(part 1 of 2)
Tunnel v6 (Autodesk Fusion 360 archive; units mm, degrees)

design "Tunnel" references "Air_intake", "Electronics Housing", "fan housing", "Air_Strainer_holder", "Air_out_Strainer", "HC002", "Testing section", "Fam2defuser", "M4x30 Hex"
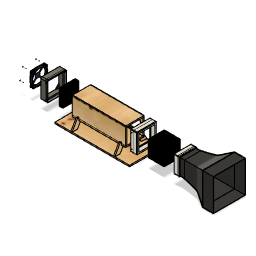
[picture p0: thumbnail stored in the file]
component_insert "Component Insert1"
component_insert "Component Insert2"
component_insert "Component Insert3"
component_insert "Component Insert4"
component_insert "Component Insert6"
component_insert "Component Insert8"
component_insert "Component Insert9"
component_insert "Component Insert10"
component_insert "Component Insert11"
component_insert "Component Insert12"
component_insert "Component Insert13"
component_insert "Component Insert14"

design "M4x30 Hex"
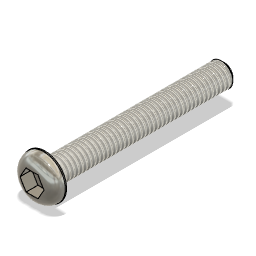
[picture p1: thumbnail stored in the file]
sketch "Sketch1" plane through (0, 0, 0) normal (0, 0, 1) x axis (1, 0, 0)
  circle C1 centre (0, 0) radius 2
  point P1 (0, 0)
  point P2 (0, 0)
  coincident P1 P2
  dimension "d1" diameter C1 = 4
extrude "Extrude1" new body sketch "Sketch1" along normal blind 30
sketch "Sketch2" plane through (0, 0, 30) normal (0, 0, 1) x axis (1, 0, 0)
  circle C1 centre (0, 0) radius 2
  circle C2 centre (0, 0) radius 3.62
  point P1 (0, 0)
  point P3 (0, 0)
  coincident P1 P3
  dimension "d4" diameter C2 = 7.24
extrude "Extrude2" add sketch "Sketch2" along normal blind 2.2
fillet "Fillet1" radius 2
sketch "Sketch3" plane through (0, 0, 32.2) normal (0, 0, 1) x axis (1, 0, 0)
  line L1 (0, -1.62) -> (0, 1.62)
  line L2 (1.62, 0) -> (-1.62, 0)
  line L3 (-1.0142, 1.7238) -> (0.9857, 1.7402)
  line L4 (-1.9999, -0.0164) -> (-1.0142, 1.7238)
  line L5 (-0.9857, -1.7402) -> (-1.9999, -0.0164)
  line L6 (1.0142, -1.7238) -> (-0.9857, -1.7402)
  line L7 (1.9999, 0.0164) -> (1.0142, -1.7238)
  line L8 (0.9857, 1.7402) -> (1.9999, 0.0164)
  circle C1 centre (0, 0) radius 1.62
  point P3 (0, 1.62)
  point P4 (0, -1.62)
  point P5 (-1.62, 0)
  point P6 (1.62, 0)
  point P1 (0, 0)
  point P13 (0, 0)
  point P7 (0.9857, 1.7402)
  coincident C1 P3
  coincident C1 P4
  vertical L1
  coincident C1 P5
  coincident C1 P6
  perpendicular L1 L2
  coincident P1 P13
  dimension "d9" distance P7 P13 = 2
extrude "Extrude3" cut sketch "Sketch3" profile of C1 L3 L4 L5 L6 L7 L8 against normal blind 2
thread "Thread1" ThreadOffset 0 ThreadLength 10
chamfer "Chamfer1" distance 0.5

design "PBC"
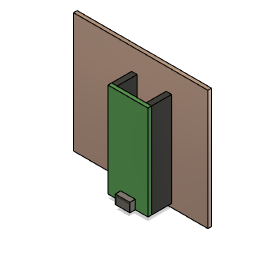
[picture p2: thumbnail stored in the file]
sketch "Sketch1" plane through (0, 0, 0) normal (0, 0, 1) x axis (1, 0, 0)
  line L1 (74, 0) -> (0, 0)
  line L2 (74, 66) -> (74, 0)
  line L3 (0, 66) -> (74, 66)
  line L4 (0, 0) -> (0, 66)
  point P1 (0, 0)
  point P2 (0, 0)
  point P3 (74, 0)
  point P4 (74, 66)
  point P5 (0, 66)
  horizontal L1
  vertical L2
  horizontal L3
  vertical L4
  coincident P1 P2
  dimension "d1" distance P3 P4 = 66
  dimension "d2" distance P4 P5 = 74
extrude "Extrude1" new body sketch "Sketch1" along normal blind 2
sketch "Sketch2" plane through (0, 0, 2) normal (0, 0, 1) x axis (1, 0, 0)
  line L1 (0, 0) -> (0, 66)
  line L2 (74, 0) -> (0, 0)
  line L3 (74, 66) -> (74, 0)
  line L4 (0, 66) -> (74, 66)
  line L5 (54, 54) -> (51, 54)
  line L6 (54, 2) -> (54, 54)
  line L7 (51, 2) -> (54, 2)
  line L8 (51, 54) -> (51, 2)
  line L9 (35, 54) -> (32, 54)
  line L10 (35, 2) -> (35, 54)
  line L11 (32, 2) -> (35, 2)
  line L12 (32, 54) -> (32, 2)
  point P10 (32, 54)
  point P11 (35, 54)
  point P12 (35, 2)
  point P7 (54, 54)
  point P8 (54, 2)
  horizontal L5
  vertical L6
  horizontal L7
  vertical L8
  horizontal L9
  vertical L10
  horizontal L11
  vertical L12
  dimension "d5" distance L3 L6 = 20
  dimension "d6" distance L6 L8 = 3
  dimension "d7" distance P10 P11 = 3
  dimension "d8" distance L6 L12 = 22
  dimension "d9" distance P10 P12 = 52
  dimension "d10" distance P7 P8 = 52
  dimension "d11" distance L4 P10 = 12
  dimension "d12" distance L4 L5 = 12
extrude "Extrude2" new body sketch "Sketch2" profile of L5 L6 L7 L8 L9 L10 L11 L12 along normal blind 11
work_plane "WorkPlane1" AlongDistance 0
sketch "Sketch3" plane through (0, 0, 13) normal (0, 0, 1) x axis (1, 0, 0)
  line L1 (32, 2) -> (32, 54)
  line L2 (54, 54) -> (54, 2)
  line L3 (54, 54) -> (32, 54)
  line L4 (54, 2) -> (54, 54)
  line L5 (32, 2) -> (54, 2)
  line L6 (32, 54) -> (32, 2)
  point P4 (54, 2)
  point P8 (54, 2)
  point P2 (32, 54)
  point P6 (32, 54)
  horizontal L3
  vertical L4
  horizontal L5
  vertical L6
  coincident P4 P8
  coincident P2 P6
extrude "Extrude3" new body sketch "Sketch3" along normal blind 2
sketch "Sketch4" plane through (0, 0, 15) normal (0, 0, 1) x axis (1, 0, 0)
  line L1 (54, 2) -> (32, 2)
  line L2 (54, 54) -> (54, 2)
  line L3 (32, 54) -> (54, 54)
  line L4 (32, 2) -> (32, 54)
  line L5 (43, 54) -> (43, 2)
  line L6 (47, 2) -> (39, 2)
  line L7 (47, 7) -> (47, 2)
  line L8 (39, 7) -> (47, 7)
  line L9 (39, 2) -> (39, 7)
  point P6 (43, 2)
  point P7 (43, 54)
  point P8 (39, 2)
  point P11 (39, 7)
  point P10 (47, 7)
  midpoint L1 P6
  midpoint L3 P7
  horizontal L6
  vertical L7
  horizontal L8
  vertical L9
  coincident L1 P8
  symmetric L5 L7 L9
  dimension "d18" distance P8 P11 = 5
  dimension "d19" distance P10 P11 = 8
extrude "Extrude4" new body sketch "Sketch4" profile of L1 L5 L6 L7 L8 L9 along normal blind 3
sketch "Sketch5" plane through (0, 2, 0) normal (0, -1, 0) x axis (1, 0, 0)
  line L1 (47, 15) -> (39, 15)
  line L2 (47, 18) -> (47, 15)
  line L3 (39, 18) -> (47, 18)
  line L4 (39, 15) -> (39, 18)
  line L5 (45.5, 17.2106) -> (40.5, 17.2106)
  line L6 (45.5, 16.6106) -> (45.5, 17.2106)
  line L7 (40.5, 16.6106) -> (45.5, 16.6106)
  line L8 (40.5, 17.2106) -> (40.5, 16.6106)
  line L9 (43, 15) -> (43, 18)
  line L10 (46.5833, 17.6974) -> (39.4167, 17.6974)
  line L11 (46.5833, 15.3264) -> (46.5833, 17.6974)
  line L12 (39.4167, 15.3264) -> (46.5833, 15.3264)
  line L13 (39.4167, 17.6974) -> (39.4167, 15.3264)
  point P10 (43, 18)
  point P11 (43, 15)
  point P6 (40.5, 17.2106)
  point P7 (45.5, 17.2106)
  horizontal L5
  vertical L6
  horizontal L7
  vertical L8
  midpoint L3 P10
  midpoint L1 P11
  symmetric L6 L8 L9
  horizontal L10
  vertical L11
  horizontal L12
  vertical L13
  symmetric L9 L11 L13
  dimension "d22" distance L5 L7 = 0.6
  dimension "d23" distance P6 P7 = 5
  dimension "d24" distance L1 L7 = 1.6106
  dimension "d25" distance L1 L12 = 0.3264
  dimension "d26" distance L4 L13 = 0.4167
  dimension "d27" distance L10 L12 = 2.371
extrude "Extrude5" cut sketch "Sketch5" profile of L5 L6 L7 L8 L9 L10 L11 L12 L13 against normal blind 4
sketch "Sketch6" plane through (0, 0, 0) normal (0, 1, 0) x axis (1, 0, 0)

design "Air_Strainer_holder"
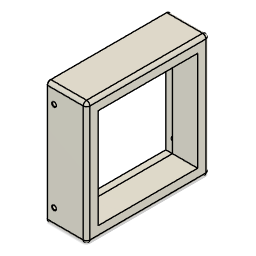
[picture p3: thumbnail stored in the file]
named bodies: "Airstrinder Holder"

design "HC002"
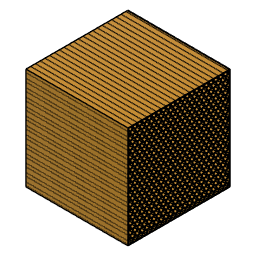
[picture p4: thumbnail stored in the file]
sketch "Sketch1" plane through (0, 0, 0) normal (1, 0, 0) x axis (0, 0, -1)
  line L1 (-75, 75) -> (75, 75)
  line L2 (-75, -75) -> (-75, 75)
  line L3 (75, -75) -> (-75, -75)
  line L4 (75, 75) -> (75, -75)
  line L5 (-75, -75) -> (75, 75)
  line L6 (75, -75) -> (-75, 75)
  line L7 (-71.3532, -71.3532) -> (0, 0)
  line L8 (-68.3532, -69.6211) -> (-68.3532, -73.0852)
  line L9 (-71.3532, -67.8891) -> (-68.3532, -69.6211)
  line L10 (-74, -69.4172) -> (-71.3532, -67.8891)
  line L11 (-72.7687, -74) -> (-74, -73.2891)
  line L12 (-68.3532, -73.0852) -> (-69.9376, -74)
  line L13 (-67.7706, -68.8181) -> (-70.7706, -67.0861)
  line L14 (-64.7706, -67.0861) -> (-67.7706, -68.8181)
  line L15 (-70.7706, -67.0861) -> (-70.7706, -63.622)
  line L16 (-64.7706, -63.622) -> (-64.7706, -67.0861)
  line L17 (-67.7706, -61.8899) -> (-64.7706, -63.622)
  line L18 (-70.7706, -63.622) -> (-67.7706, -61.8899)
  line L19 (-71.3532, -79.3958) -> (-71.3532, -71.3532)
  line L20 (-67.3532, -73.0852) -> (-67.3532, -69.6211)
  line L21 (-65.7687, -74) -> (-67.3532, -73.0852)
  line L22 (-61.3532, -73.0852) -> (-62.9376, -74)
  line L23 (-61.3532, -69.6211) -> (-61.3532, -73.0852)
  line L24 (-64.3532, -67.8891) -> (-61.3532, -69.6211)
  line L25 (-67.3532, -69.6211) -> (-64.3532, -67.8891)
  line L26 (-57.7706, -63.622) -> (-57.7706, -67.0861)
  line L27 (-60.7706, -61.8899) -> (-57.7706, -63.622)
  line L28 (-63.7706, -63.622) -> (-60.7706, -61.8899)
  line L29 (-63.7706, -67.0861) -> (-63.7706, -63.622)
  line L30 (-60.7706, -68.8181) -> (-63.7706, -67.0861)
  line L31 (-57.7706, -67.0861) -> (-60.7706, -68.8181)
  line L32 (-50.3532, -67.8891) -> (-47.3532, -69.6211)
  line L33 (-53.3532, -69.6211) -> (-50.3532, -67.8891)
  line L34 (-51.7687, -74) -> (-53.3532, -73.0852)
  line L35 (-47.3532, -73.0852) -> (-48.9376, -74)
  line L36 (-47.3532, -69.6211) -> (-47.3532, -73.0852)
  line L37 (-53.3532, -73.0852) -> (-53.3532, -69.6211)
  line L38 (-54.3532, -73.0852) -> (-55.9376, -74)
  line L39 (-57.3532, -67.8891) -> (-54.3532, -69.6211)
  line L40 (-60.3532, -69.6211) -> (-57.3532, -67.8891)
  line L41 (-58.7687, -74) -> (-60.3532, -73.0852)
  line L42 (-60.3532, -73.0852) -> (-60.3532, -69.6211)
  line L43 (-54.3532, -69.6211) -> (-54.3532, -73.0852)
  line L44 (-36.3532, -67.8891) -> (-33.3532, -69.6211)
  line L45 (-39.3532, -69.6211) -> (-36.3532, -67.8891)
  line L46 (-37.7687, -74) -> (-39.3532, -73.0852)
  line L47 (-33.3532, -73.0852) -> (-34.9376, -74)
  line L48 (-33.3532, -69.6211) -> (-33.3532, -73.0852)
  line L49 (-39.3532, -73.0852) -> (-39.3532, -69.6211)
  line L50 (-40.3532, -73.0852) -> (-41.9376, -74)
  line L51 (-43.3532, -67.8891) -> (-40.3532, -69.6211)
  line L52 (-46.3532, -69.6211) -> (-43.3532, -67.8891)
  line L53 (-44.7687, -74) -> (-46.3532, -73.0852)
  line L54 (-46.3532, -73.0852) -> (-46.3532, -69.6211)
  line L55 (-40.3532, -69.6211) -> (-40.3532, -73.0852)
  line L56 (-53.7706, -61.8899) -> (-50.7706, -63.622)
  line L57 (-56.7706, -63.622) -> (-53.7706, -61.8899)
  line L58 (-56.7706, -67.0861) -> (-56.7706, -63.622)
  line L59 (-53.7706, -68.8181) -> (-56.7706, -67.0861)
  line L60 (-50.7706, -67.0861) -> (-53.7706, -68.8181)
  line L61 (-50.7706, -63.622) -> (-50.7706, -67.0861)
  line L62 (-49.7706, -67.0861) -> (-49.7706, -63.622)
  line L63 (-46.7706, -68.8181) -> (-49.7706, -67.0861)
  line L64 (-43.7706, -67.0861) -> (-46.7706, -68.8181)
  line L65 (-43.7706, -63.622) -> (-43.7706, -67.0861)
  line L66 (-46.7706, -61.8899) -> (-43.7706, -63.622)
  line L67 (-49.7706, -63.622) -> (-46.7706, -61.8899)
  line L68 (-39.7706, -61.8899) -> (-36.7706, -63.622)
  line L69 (-42.7706, -63.622) -> (-39.7706, -61.8899)
  line L70 (-42.7706, -67.0861) -> (-42.7706, -63.622)
  line L71 (-39.7706, -68.8181) -> (-42.7706, -67.0861)
  line L72 (-36.7706, -67.0861) -> (-39.7706, -68.8181)
  line L73 (-36.7706, -63.622) -> (-36.7706, -67.0861)
  line L74 (-35.7706, -67.0861) -> (-35.7706, -63.622)
  line L75 (-32.7706, -68.8181) -> (-35.7706, -67.0861)
  line L76 (-29.7706, -67.0861) -> (-32.7706, -68.8181)
  line L77 (-29.7706, -63.622) -> (-29.7706, -67.0861)
  line L78 (-32.7706, -61.8899) -> (-29.7706, -63.622)
  line L79 (-35.7706, -63.622) -> (-32.7706, -61.8899)
  line L80 (9.2294, -61.8899) -> (12.2294, -63.622)
  line L81 (12.2294, -63.622) -> (12.2294, -67.0861)
  line L82 (-0.7706, -63.622) -> (2.2294, -61.8899)
  line L83 (2.6468, -73.0852) -> (2.6468, -69.6211)
  line L84 (-4.3532, -69.6211) -> (-1.3532, -67.8891)
  line L85 (1.6468, -69.6211) -> (1.6468, -73.0852)
  line L86 (-14.7706, -63.622) -> (-11.7706, -61.8899)
  line L87 (-25.7706, -61.8899) -> (-22.7706, -63.622)
  line L88 (-5.3532, -73.0852) -> (-6.9376, -74)
  line L89 (-2.7687, -74) -> (-4.3532, -73.0852)
  line L90 (-7.7706, -63.622) -> (-4.7706, -61.8899)
  line L91 (-0.7706, -67.0861) -> (-0.7706, -63.622)
  line L92 (5.2294, -67.0861) -> (2.2294, -68.8181)
  line L93 (-8.3532, -67.8891) -> (-5.3532, -69.6211)
  line L94 (2.2294, -68.8181) -> (-0.7706, -67.0861)
  line L95 (2.6468, -69.6211) -> (5.6468, -67.8891)
  line L96 (-4.7706, -61.8899) -> (-1.7706, -63.622)
  line L97 (8.6468, -69.6211) -> (8.6468, -73.0852)
  line L98 (-21.7706, -63.622) -> (-18.7706, -61.8899)
  line L99 (1.6468, -73.0852) -> (0.0624, -74)
  line L100 (-7.7706, -67.0861) -> (-7.7706, -63.622)
  line L101 (-18.7706, -61.8899) -> (-15.7706, -63.622)
  line L102 (5.2294, -63.622) -> (5.2294, -67.0861)
  line L103 (4.2313, -74) -> (2.6468, -73.0852)
  line L104 (-28.7706, -63.622) -> (-25.7706, -61.8899)
  line L105 (2.2294, -61.8899) -> (5.2294, -63.622)
  line L106 (6.2294, -63.622) -> (9.2294, -61.8899)
  line L107 (-11.7706, -61.8899) -> (-8.7706, -63.622)
  line L108 (12.2294, -67.0861) -> (9.2294, -68.8181)
  line L109 (-1.3532, -67.8891) -> (1.6468, -69.6211)
  line L110 (-8.7706, -67.0861) -> (-11.7706, -68.8181)
  line L111 (-11.3532, -69.6211) -> (-8.3532, -67.8891)
  line L112 (-9.7687, -74) -> (-11.3532, -73.0852)
  line L113 (-1.7706, -63.622) -> (-1.7706, -67.0861)
  line L114 (8.6468, -73.0852) -> (7.0624, -74)
  line L115 (-1.7706, -67.0861) -> (-4.7706, -68.8181)
  line L116 (5.6468, -67.8891) -> (8.6468, -69.6211)
  line L117 (-4.7706, -68.8181) -> (-7.7706, -67.0861)
  line L118 (-11.7706, -68.8181) -> (-14.7706, -67.0861)
  line L119 (6.2294, -67.0861) -> (6.2294, -63.622)
  line L120 (-8.7706, -63.622) -> (-8.7706, -67.0861)
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  point P6 (0, 0)
  point P1 (0, 0)
  point P7 (0, 0)
  point P8 (-71.3532, -71.3532)
  point P12 (-71.3532, -71.3532)
  point P3957 (0, 0)
  point P3958 (-75, 21.9776)
  point P3971 (-75, 45.9776)
  point P3981 (-74.3532, 74.3532)
  point P3982 (-75, 63.3143)
  point P3998 (75, 56.5105)
  point P4 (-75, -75)
  point P5 (75, -75)
  point P3 (-75, 75)
  point P15 (-67.8532, -65.291)
  point P26 (-64.3532, -71.3532)
  point P3955 (-74, -74)
  point P3956 (74, -74)
  point P3954 (-74, 74)
  horizontal L1
  perpendicular L1 L2
  parallel L1 L3
  parallel L2 L4
  coincident L5 P6
  coincident L6 P6
  coincident P1 P6
  coincident P6 P7
  vertical L8
  coincident P8 P12
  vertical L19
  coincident P6 P3957
  coincident L2 P3958
  coincident L2 P3971
  coincident L6 P3981
  coincident L2 P3982
  coincident L4 P3998
  dimension "d1" distance P4 P5 = 150
  dimension "d2" distance P3 P4 = 150
  dimension "d10" distance P12 P15 = 7
  dimension "d15" distance P15 P26 = 7
  dimension "d56" distance P3955 P3956 = 148
  dimension "d57" distance P3954 P3955 = 148
  dimension "d58" distance P12 L8 = 3
  dimension "d18" R-Pattern2-uDistance = 7
  dimension "d19" R-Pattern2-vDistance = 0
  dimension "d26" R-Pattern4-uDistance = 14
  dimension "d27" R-Pattern4-vDistance = 0
extrude "Extrude1" new body sketch "Sketch1" along normal blind 150

design "OLED"
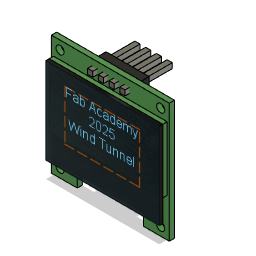
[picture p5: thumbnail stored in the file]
sketch "Sketch1" plane through (0, 0, 0) normal (0, 0, 1) x axis (1, 0, 0)
  line L1 (-13.7, 13.9) -> (13.7, 13.9)
  line L2 (-13.7, -13.9) -> (-13.7, 13.9)
  line L3 (13.7, 13.9) -> (13.7, -13.9)
  line L4 (-13.7, -13.9) -> (13.7, 13.9)
  line L5 (13.7, -13.9) -> (-13.7, 13.9)
  line L6 (13.7, 0) -> (-13.7, 0)
  line L7 (-7.7, -11.9) -> (-7.7, -13.9)
  line L8 (6.7, -10.9) -> (-6.7, -10.9)
  line L9 (7.7, -13.9) -> (7.7, -11.9)
  line L10 (-7.7, -13.9) -> (-13.7, -13.9)
  line L11 (13.7, -13.9) -> (7.7, -13.9)
  circle C1 centre (-11.7, 11.9) radius 0.95
  circle C2 centre (11.7, 11.9) radius 0.95
  circle C3 centre (-11.7, -11.9) radius 0.95
  circle C4 centre (11.7, -11.9) radius 0.95
  arc A1 centre (-6.7, -11.9) radius 1 clockwise from (-7.7, -11.9) to (-6.7, -10.9)
  arc A2 centre (6.7, -11.9) radius 1 clockwise from (6.7, -10.9) to (7.7, -11.9)
  point P6 (0, 0)
  point P1 (0, 0)
  point P9 (-13.7, 0)
  point P10 (13.7, 0)
  point P14 (7.7, -13.9)
  point P3 (-13.7, 13.9)
  point P4 (-13.7, -13.9)
  point P2 (13.7, 13.9)
  point P7 (-11.7, 11.9)
  point P8 (11.7, 11.9)
  horizontal L1
  perpendicular L1 L2
  parallel L1 L10
  parallel L2 L3
  coincident L4 P6
  coincident L5 P6
  coincident P1 P6
  midpoint L2 P9
  midpoint L3 P10
  symmetric C1 L6 C3
  symmetric C2 L6 C4
  perpendicular L7 L10
  perpendicular L7 L8
  coincident P14 L10
  perpendicular L9 L10
  tangent L7 A1
  tangent L8 A1
  tangent L8 A2
  tangent L9 A2
  equal A1 A2
  collinear L10 L11
  dimension "d1" distance P3 P4 = 27.8
  dimension "d2" distance P2 P3 = 27.4
  dimension "d3" diameter C1 = 1.9
  dimension "d4" distance L1 P7 = 2
  dimension "d5" distance L2 P7 = 2
  dimension "d6" diameter C2 = 1.9
  dimension "d7" distance L1 P8 = 2
  dimension "d8" distance L3 P8 = 2
  dimension "d17" radius A1 = 1
  dimension "d18" distance L2 L7 = 6
  dimension "d19" distance L3 L9 = 6
  dimension "d20" distance L8 L10 = 3
extrude "Extrude1" new body sketch "Sketch1" profile of L1 L2 L11 L3 C1 C2 C3 C4 along normal blind 1.2
sketch "Sketch2" plane through (0, 0, 1.2) normal (0, 0, 1) x axis (1, 0, 0)
  line L1 (13.7, 13.9) -> (13.7, -13.9)
  line L2 (-13.7, 13.9) -> (13.7, 13.9)
  line L3 (-13.7, -13.9) -> (-13.7, 13.9)
  line L4 (13.7, -13.9) -> (7.7, -13.9)
  line L5 (13.2, 9.9) -> (-13.2, 9.9)
  line L6 (13.2, -4.9) -> (13.2, 9.9)
  line L7 (-13.2, -4.9) -> (13.2, -4.9)
  line L8 (-13.2, 9.9) -> (-13.2, -4.9)
  line L9 (7.7, -13.9) -> (7.7, -11.9)
  line L10 (-7.7, -13.9) -> (-13.7, -13.9)
  line L11 (-7.7, -11.9) -> (-7.7, -13.9)
  line L12 (6.7, -10.9) -> (-6.7, -10.9)
  circle C1 centre (11.7, -11.9) radius 0.95
  circle C2 centre (-11.7, -11.9) radius 0.95
  circle C3 centre (-11.7, 11.9) radius 0.95
  circle C4 centre (11.7, 11.9) radius 0.95
  arc A1 centre (-6.7, -11.9) radius 1 clockwise from (-7.7, -11.9) to (-6.7, -10.9)
  arc A2 centre (6.7, -11.9) radius 1 clockwise from (6.7, -10.9) to (7.7, -11.9)
  horizontal L5
  vertical L6
  horizontal L7
  vertical L8
  dimension "d11" distance L2 L5 = 4
  dimension "d12" distance L4 L7 = 9
  dimension "d13" distance L3 L8 = 0.5
  dimension "d14" distance L1 L6 = 0.5
extrude "Extrude2" add sketch "Sketch2" + "Sketch3" profile of S1:L5 S1:L6 S1:L7 S1:L8 blind 1
sketch "Sketch3" plane through (0, 0, 2.2) normal (0, 0, 1) x axis (1, 0, 0)
  line L1 (13.2, -4.9) -> (-13.2, -4.9)
  line L2 (13.2, 9.9) -> (13.2, -4.9)
  line L3 (-13.2, 9.9) -> (13.2, 9.9)
  line L4 (-13.2, -4.9) -> (-13.2, 9.9)
  line L5 (13.2, 9.9) -> (-13.2, 9.9)
  line L6 (13.2, -10.1) -> (13.2, 9.9)
  line L7 (-13.2, -10.1) -> (13.2, -10.1)
  line L8 (-13.2, 9.9) -> (-13.2, -10.1)
  point P5 (-13.2, 9.9)
  point P6 (-13.2, 9.9)
  point P7 (13.2, 9.9)
  point P8 (13.2, -10.1)
  horizontal L5
  vertical L6
  horizontal L7
  vertical L8
  coincident P5 P6
  dimension "d21" distance P7 P8 = 20
  dimension "d22" distance L6 L8 = 26.4
extrude "Extrude3" new body sketch "Sketch3" along normal blind 0.8
sketch "Sketch4" plane through (0, 0, 0) normal (0, 0, -1) x axis (-1, 0, 0)
  line L1 (-7.7, -11.9) -> (-7.7, -13.9)
  line L2 (6.7, -10.9) -> (-6.7, -10.9)
  line L3 (7.7, -13.9) -> (7.7, -11.9)
  line L4 (13.7, -13.9) -> (7.7, -13.9)
  line L5 (13.7, 13.9) -> (13.7, -13.9)
  line L6 (-13.7, 13.9) -> (13.7, 13.9)
  line L7 (-13.7, -13.9) -> (-13.7, 13.9)
  line L8 (-7.7, -13.9) -> (-13.7, -13.9)
  line L9 (5, 12.9) -> (-5, 12.9)
  line L10 (5, 10.7) -> (5, 12.9)
  line L11 (-5, 10.7) -> (5, 10.7)
  line L12 (-5, 12.9) -> (-5, 10.7)
  line L13 (0, -10.9) -> (0, 13.9)
  circle C1 centre (-11.7, -11.9) radius 0.95
  circle C2 centre (-11.7, 11.9) radius 0.95
  circle C3 centre (11.7, -11.9) radius 0.95
  circle C4 centre (11.7, 11.9) radius 0.95
  arc A1 centre (-6.7, -11.9) radius 1 clockwise from (-7.7, -11.9) to (-6.7, -10.9)
  arc A2 centre (6.7, -11.9) radius 1 clockwise from (6.7, -10.9) to (7.7, -11.9)
  point P22 (0, 13.9)
  point P23 (0, -10.9)
  point P20 (5, 10.7)
  point P21 (-5, 10.7)
  point P18 (-5, 12.9)
  horizontal L9
  vertical L10
  horizontal L11
  vertical L12
  midpoint L6 P22
  midpoint L2 P23
  dimension "d25" distance P20 P21 = 10
  dimension "d26" distance L6 L9 = 1
  dimension "d27" distance P18 P21 = 2.2
extrude "Extrude4" new body sketch "Sketch4" profile of L9 L10 L11 L12 along normal blind 2.8
sketch "Sketch5" plane through (0, 0, -2.8) normal (0, 0, -1) x axis (-1, 0, 0)
  line L1 (5, 10.7) -> (-5, 10.7)
  line L2 (5, 12.9) -> (5, 10.7)
  line L3 (-5, 12.9) -> (5, 12.9)
  line L4 (-5, 10.7) -> (-5, 12.9)
  line L5 (5, 11.8) -> (-5, 11.8)
  line L6 (-3.2, 12.4) -> (-4.4, 12.4)
  line L7 (-3.2, 11.2) -> (-3.2, 12.4)
  line L8 (-4.4, 11.2) -> (-3.2, 11.2)
  line L9 (-4.4, 12.4) -> (-4.4, 11.2)
  line L10 (-0.7, 11.2) -> (-0.7, 12.4)
  line L11 (-0.7, 12.4) -> (-1.9, 12.4)
  line L12 (-1.9, 12.4) -> (-1.9, 11.2)
  line L13 (-1.9, 11.2) -> (-0.7, 11.2)
  line L14 (1.8, 11.2) -> (1.8, 12.4)
  line L15 (1.8, 12.4) -> (0.6, 12.4)
  line L16 (0.6, 12.4) -> (0.6, 11.2)
  line L17 (0.6, 11.2) -> (1.8, 11.2)
  line L18 (4.3, 11.2) -> (4.3, 12.4)
  line L19 (4.3, 12.4) -> (3.1, 12.4)
  line L20 (3.1, 12.4) -> (3.1, 11.2)
  line L21 (3.1, 11.2) -> (4.3, 11.2)
  point P6 (-5, 11.8)
  point P7 (5, 11.8)
  point P8 (-4.4, 12.4)
  point P9 (-3.2, 12.4)
  point P10 (-3.2, 11.2)
  midpoint L4 P6
  midpoint L2 P7
  horizontal L6
  vertical L7
  horizontal L8
  vertical L9
  symmetric L5 L6 L8
  dimension "d30" distance P8 P9 = 1.2
  dimension "d31" distance P9 P10 = 1.2
  dimension "d32" distance L4 L9 = 0.6
  dimension "d35" R-Pattern1-uDistance = 7.5
  dimension "d36" R-Pattern1-vDistance = 0
extrude "Extrude5" new body sketch "Sketch5" profile of L6 L7 L8 L9 L10 L11 L12 L13 L14 L15 L16 L17 L18 L19 L20 L21 along normal blind 6 and against normal blind 5
sketch "Sketch6" plane through (0, 0, 3) normal (0, 0, 1) x axis (1, 0, 0)
  dimension "d41" = 2

design "Electronics Housing" references "PBC", "OLED", "LRS-35-12"
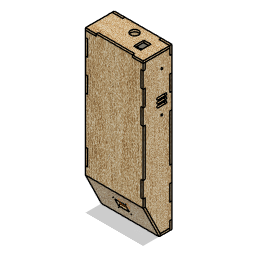
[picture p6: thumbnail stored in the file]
named bodies: "Floor", "front", "Back", "Top", "Display Pannel", "Left Side", "Right side"

design "Air_intake"
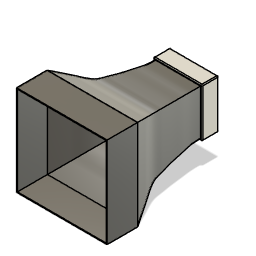
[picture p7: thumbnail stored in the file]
sketch "Sketch1" plane through (0, 0, 0) normal (0, 0, 1) x axis (1, 0, 0)
  line L1 (-150, 150) -> (150, 150)
  line L2 (-150, -150) -> (-150, 150)
  line L3 (150, -150) -> (-150, -150)
  line L4 (150, 150) -> (150, -150)
  line L5 (-150, -150) -> (150, 150)
  line L6 (150, -150) -> (-150, 150)
  point P6 (0, 0)
  point P1 (0, 0)
  point P4 (-150, -150)
  point P5 (150, -150)
  point P3 (-150, 150)
  horizontal L1
  perpendicular L1 L2
  parallel L1 L3
  parallel L2 L4
  coincident L5 P6
  coincident L6 P6
  coincident P1 P6
  dimension "d1" distance P4 P5 = 300
  dimension "d2" distance P3 P4 = 300
work_plane "WorkPlane1" AlongDistance -50
sketch "Sketch2" plane through (0, 0, -50) normal (0, 0, 1) x axis (1, 0, 0)
  line L1 (-125, 125) -> (125, 125)
  line L2 (-125, -125) -> (-125, 125)
  line L3 (125, -125) -> (-125, -125)
  line L4 (125, 125) -> (125, -125)
  line L5 (-125, -125) -> (125, 125)
  line L6 (125, -125) -> (-125, 125)
  point P6 (0, 0)
  point P1 (0, 0)
  point P4 (-125, -125)
  point P5 (125, -125)
  point P3 (-125, 125)
  horizontal L1
  perpendicular L1 L2
  parallel L1 L3
  parallel L2 L4
  coincident L5 P6
  coincident L6 P6
  coincident P1 P6
  dimension "d4" distance P4 P5 = 250
  dimension "d5" distance P3 P4 = 250
work_plane "WorkPlane2" sketch "Sketch1" AlongDistance -300
sketch "Sketch3" plane through (0, 0, -300) normal (0, 0, 1) x axis (1, 0, 0)
  line L1 (-75, 75) -> (75, 75)
  line L2 (-75, -75) -> (-75, 75)
  line L3 (75, -75) -> (-75, -75)
  line L4 (75, 75) -> (75, -75)
  line L5 (-75, -75) -> (75, 75)
  line L6 (75, -75) -> (-75, 75)
  point P6 (0, 0)
  point P1 (0, 0)
  point P4 (-75, -75)
  point P5 (75, -75)
  point P3 (-75, 75)
  horizontal L1
  perpendicular L1 L2
  parallel L1 L3
  parallel L2 L4
  coincident L5 P6
  coincident L6 P6
  coincident P1 P6
  dimension "d7" distance P4 P5 = 150
  dimension "d8" distance P3 P4 = 150
work_plane "WorkPlane3" sketch "Sketch2" AlongDistance -65
sketch "Sketch4" plane through (0, 0, -115) normal (0, 0, 1) x axis (1, 0, 0)
  line L1 (-95, 95) -> (95, 95)
  line L2 (-95, -95) -> (-95, 95)
  line L3 (95, -95) -> (-95, -95)
  line L4 (95, 95) -> (95, -95)
  line L5 (-95, -95) -> (95, 95)
  line L6 (95, -95) -> (-95, 95)
  point P6 (0, 0)
  point P1 (0, 0)
  point P4 (-95, -95)
  point P5 (95, -95)
  point P3 (-95, 95)
  horizontal L1
  perpendicular L1 L2
  parallel L1 L3
  parallel L2 L4
  coincident L5 P6
  coincident L6 P6
  coincident P1 P6
  dimension "d10" distance P4 P5 = 190
  dimension "d11" distance P3 P4 = 190
work_plane "WorkPlane4" sketch "Sketch4" AlongDistance -30
sketch "Sketch5" plane through (0, 0, -145) normal (0, 0, 1) x axis (1, 0, 0)
  line L1 (-90, 90) -> (90, 90)
  line L2 (-90, -90) -> (-90, 90)
  line L3 (90, -90) -> (-90, -90)
  line L4 (90, 90) -> (90, -90)
  line L5 (-90, -90) -> (90, 90)
  line L6 (90, -90) -> (-90, 90)
  point P6 (0, 0)
  point P1 (0, 0)
  point P4 (-90, -90)
  point P5 (90, -90)
  point P3 (-90, 90)
  horizontal L1
  perpendicular L1 L2
  parallel L1 L3
  parallel L2 L4
  coincident L5 P6
  coincident L6 P6
  coincident P1 P6
  dimension "d13" distance P4 P5 = 180
  dimension "d14" distance P3 P4 = 180
work_plane "WorkPlane5" sketch "Sketch5" AlongDistance -30
sketch "Sketch6" plane through (0, 0, -175) normal (0, 0, 1) x axis (1, 0, 0)
  line L1 (-85, 85) -> (85, 85)
  line L2 (-85, -85) -> (-85, 85)
  line L3 (85, -85) -> (-85, -85)
  line L4 (85, 85) -> (85, -85)
  line L5 (-85, -85) -> (85, 85)
  line L6 (85, -85) -> (-85, 85)
  point P6 (0, 0)
  point P1 (0, 0)
  point P4 (-85, -85)
  point P5 (85, -85)
  point P3 (-85, 85)
  horizontal L1
  perpendicular L1 L2
  parallel L1 L3
  parallel L2 L4
  coincident L5 P6
  coincident L6 P6
  coincident P1 P6
  dimension "d16" distance P4 P5 = 170
  dimension "d17" distance P3 P4 = 170
work_plane "WorkPlane6" sketch "Sketch6" AlongDistance -40
sketch "Sketch7" plane through (0, 0, -215) normal (0, 0, 1) x axis (1, 0, 0)
  line L1 (80, 80) -> (-80, 80)
  line L2 (80, -80) -> (80, 80)
  line L3 (-80, -80) -> (80, -80)
  line L4 (-80, 80) -> (-80, -80)
  line L5 (80, -80) -> (-80, 80)
  line L6 (-80, -80) -> (80, 80)
  point P6 (0, 0)
  point P1 (0, 0)
  point P4 (80, -80)
  point P5 (-80, -80)
  point P3 (80, 80)
  horizontal L1
  perpendicular L1 L2
  parallel L1 L3
  parallel L2 L4
  coincident L5 P6
  coincident L6 P6
  coincident P1 P6
  dimension "d19" distance P4 P5 = 160
  dimension "d20" distance P3 P4 = 160
work_plane "WorkPlane7" sketch "Sketch3" AlongDistance 42.5 (= "( 85 / 2 ) * 1 mm")
sketch "Sketch8" plane through (0, 0, -257.5) normal (0, 0, 1) x axis (1, 0, 0)
  line L1 (-75, 75) -> (75, 75)
  line L2 (-75, -75) -> (-75, 75)
  line L3 (75, -75) -> (-75, -75)
  line L4 (75, 75) -> (75, -75)
  line L5 (-75, -75) -> (75, 75)
  line L6 (75, -75) -> (-75, 75)
  point P6 (0, 0)
  point P1 (0, 0)
  point P4 (-75, -75)
  point P5 (75, -75)
  point P3 (-75, 75)
  horizontal L1
  perpendicular L1 L2
  parallel L1 L3
  parallel L2 L4
  coincident L5 P6
  coincident L6 P6
  coincident P1 P6
  dimension "d22" distance P4 P5 = 150
  dimension "d23" distance P3 P4 = 150
loft "Loft1" bodies "intake"
shell "Shell1" innerThickness 2
extrude "Extrude1" add of existing geometry blind 10
sketch "Sketch9" plane through (0, 0, -310) normal (0, 0, -1) x axis (-1, 0, 0)
  line L1 (-75, -75) -> (-75, 75)
  line L2 (75, -75) -> (-75, -75)
  line L3 (75, 75) -> (75, -75)
  line L4 (-75, 75) -> (75, 75)
  line L5 (-74, 74) -> (74, 74)
  line L6 (-74, -74) -> (-74, 74)
  line L7 (74, -74) -> (-74, -74)
  line L8 (74, 74) -> (74, -74)
  line L9 (-74, -74) -> (74, 74)
  line L10 (74, -74) -> (-74, 74)
  point P10 (0, 0)
  point P1 (0, 0)
  point P8 (-74, -74)
  point P9 (74, -74)
  point P7 (-74, 74)
  horizontal L5
  perpendicular L5 L6
  parallel L5 L7
  parallel L6 L8
  coincident L9 P10
  coincident L10 P10
  coincident P1 P10
  dimension "d27" distance P8 P9 = 148
  dimension "d28" distance P7 P8 = 148
extrude "Extrude2" cut sketch "Sketch9" profile of L5 L6 L7 L8 against normal blind 160
extrude "Extrude3" add of existing geometry blind 100
offset_faces "OffsetFaces1" distance 0.5
offset_faces "OffsetFaces2" distance 1.2
offset_faces "OffsetFaces3" distance 1.2
offset_faces "OffsetFaces4" distance 1.2
offset_faces "OffsetFaces5" distance 1.2
sketch "Sketch10" plane through (0, 0, 100) normal (0, 0, 1) x axis (1, 0, 0)
  line L1 (147.7485, -147.7485) -> (147.7485, 147.7485)
  line L2 (-147.7485, -147.7485) -> (147.7485, -147.7485)
  line L3 (-147.7485, 147.7485) -> (-147.7485, -147.7485)
  line L4 (147.7485, 147.7485) -> (-147.7485, 147.7485)
  line L5 (150.5, 150.5) -> (150.5, -150.5)
  line L6 (-150.5, 150.5) -> (150.5, 150.5)
  line L7 (-150.5, -150.5) -> (-150.5, 150.5)
  line L8 (150.5, -150.5) -> (-150.5, -150.5)
  line L9 (150.5, -150.5) -> (-150.5, -150.5)
  line L10 (150.5, 150.5) -> (150.5, -150.5)
  line L11 (-150.5, 150.5) -> (150.5, 150.5)
  line L12 (-150.5, -150.5) -> (-150.5, 150.5)
  line L13 (150.5, -150.5) -> (-150.5, 150.5)
  line L14 (-150.5, -150.5) -> (150.5, 150.5)
  line L15 (-156.5, 156.5) -> (156.5, 156.5)
  line L16 (-156.5, -156.5) -> (-156.5, 156.5)
  line L17 (156.5, -156.5) -> (-156.5, -156.5)
  line L18 (156.5, 156.5) -> (156.5, -156.5)
  line L19 (-156.5, -156.5) -> (156.5, 156.5)
  line L20 (156.5, -156.5) -> (-156.5, 156.5)
  point P7 (150.5, 150.5)
  point P12 (150.5, 150.5)
  point P9 (-150.5, -150.5)
  point P10 (-150.5, -150.5)
  point P8 (-150.5, 150.5)
  point P14 (-150.5, 150.5)
  point P6 (150.5, -150.5)
  point P15 (150.5, -150.5)
  point P16 (150.5, 150.5)
  point P21 (0, 0)
  point P1 (0, 0)
  horizontal L9
  vertical L10
  horizontal L11
  vertical L12
  coincident P7 P12
  coincident P9 P10
  coincident P8 P14
  coincident P6 P15
  coincident P7 P16
  horizontal L15
  perpendicular L15 L16
  parallel L15 L17
  parallel L16 L18
  coincident L19 P21
  coincident L20 P21
  coincident P1 P21
  dimension "d38" distance L11 L15 = 6
  dimension "d39" distance L12 L16 = 6
extrude "Extrude4" new body sketch "Sketch10" profile of L5 L6 L7 L8 L9 L10 L11 L12 L15 L16 L17 L18 against normal blind 6 bodies "strainer Frame"
sketch "Sketch11" plane through (0, 0, 100) normal (0, 0, 1) x axis (1, 0, 0)
  line L1 (-150.5, 150.5) -> (-150.5, -150.5)
  line L2 (150.5, 150.5) -> (-150.5, 150.5)
  line L3 (150.5, -150.5) -> (150.5, 150.5)
  line L4 (-150.5, -150.5) -> (150.5, -150.5)
  line L5 (156.5, 156.5) -> (156.5, -156.5)
  line L6 (-156.5, 156.5) -> (156.5, 156.5)
  line L7 (-156.5, -156.5) -> (-156.5, 156.5)
  line L8 (156.5, -156.5) -> (-156.5, -156.5)
  line L9 (-144.5, 144.5) -> (144.5, 144.5)
  line L10 (-144.5, -144.5) -> (-144.5, 144.5)
  line L11 (144.5, -144.5) -> (-144.5, -144.5)
  line L12 (144.5, 144.5) -> (144.5, -144.5)
  line L13 (-144.5, -144.5) -> (144.5, 144.5)
  line L14 (144.5, -144.5) -> (-144.5, 144.5)
  line L15 (-156.5, 156.5) -> (156.5, 156.5)
  line L16 (-156.5, -156.5) -> (-156.5, 156.5)
  line L17 (156.5, -156.5) -> (-156.5, -156.5)
  line L18 (156.5, 156.5) -> (156.5, -156.5)
  line L19 (-156.5, -156.5) -> (156.5, 156.5)
  line L20 (156.5, -156.5) -> (-156.5, 156.5)
  point P14 (0, 0)
  point P1 (0, 0)
  point P19 (0, 0)
  point P7 (156.5, 156.5)
  point P15 (156.5, 156.5)
  horizontal L9
  perpendicular L9 L10
  parallel L9 L11
  parallel L10 L12
  coincident L13 P14
  coincident L14 P14
  coincident P1 P14
  horizontal L15
  perpendicular L15 L16
  parallel L15 L17
  parallel L16 L18
  coincident L19 P19
  coincident L20 P19
  coincident P7 P15
  coincident P14 P19
  dimension "d42" distance L6 L9 = 12
  dimension "d43" distance L7 L10 = 12
extrude "Extrude5" add sketch "Sketch11" profile of L1 L2 L3 L4 L5 L6 L7 L8 L9 L10 L11 L12 L15 L16 L17 L18 along normal blind 6
sketch "Sketch13" plane through (0, 0, -310) normal (0, 0, -1) x axis (-1, 0, 0)
  line L1 (74, 74) -> (-74, 74)
  line L2 (74, -74) -> (74, 74)
  line L3 (-74, -74) -> (74, -74)
  line L4 (-74, 74) -> (-74, -74)
  line L5 (-76.2, -76.2) -> (-76.2, 76.2)
  line L6 (76.2, -76.2) -> (-76.2, -76.2)
  line L7 (76.2, 76.2) -> (76.2, -76.2)
  line L8 (-76.2, 76.2) -> (76.2, 76.2)
  line L9 (76.2, 76.2) -> (-76.2, 76.2)
  line L10 (76.2, -76.2) -> (76.2, 76.2)
  line L11 (-76.2, -76.2) -> (76.2, -76.2)
  line L12 (-76.2, 76.2) -> (-76.2, -76.2)
  line L13 (-81.2, 81.2) -> (81.2, 81.2)
  line L14 (-81.2, -81.2) -> (-81.2, 81.2)
  line L15 (81.2, -81.2) -> (-81.2, -81.2)
  line L16 (81.2, 81.2) -> (81.2, -81.2)
  line L17 (-81.2, -81.2) -> (81.2, 81.2)
  line L18 (81.2, -81.2) -> (-81.2, 81.2)
  point P8 (76.2, -76.2)
  point P12 (76.2, -76.2)
  point P6 (-76.2, 76.2)
  point P10 (-76.2, 76.2)
  point P18 (0, 0)
  point P1 (0, 0)
  horizontal L9
  vertical L10
  horizontal L11
  vertical L12
  coincident P8 P12
  coincident P6 P10
  horizontal L13
  perpendicular L13 L14
  parallel L13 L15
  parallel L14 L16
  coincident L17 P18
  coincident L18 P18
  coincident P1 P18
  dimension "d46" distance L9 L13 = 5
  dimension "d47" distance L10 L16 = 5
extrude "Extrude6" new body sketch "Sketch13" profile of L5 L6 L7 L8 L9 L10 L11 L12 L13 L14 L15 L16 against normal blind 25
sketch "Sketch14" plane through (0, 0, -310) normal (0, 0, -1) x axis (-1, 0, 0)
  line L1 (-76.2, -76.2) -> (76.2, -76.2)
  line L2 (-76.2, 76.2) -> (-76.2, -76.2)
  line L3 (76.2, 76.2) -> (-76.2, 76.2)
  line L4 (76.2, -76.2) -> (76.2, 76.2)
  line L5 (81.2, 81.2) -> (81.2, -81.2)
  line L6 (-81.2, 81.2) -> (81.2, 81.2)
  line L7 (-81.2, -81.2) -> (-81.2, 81.2)
  line L8 (81.2, -81.2) -> (-81.2, -81.2)
  line L9 (-75.25, 75.25) -> (75.25, 75.25)
  line L10 (-75.25, -75.25) -> (-75.25, 75.25)
  line L11 (75.25, -75.25) -> (-75.25, -75.25)
  line L12 (75.25, 75.25) -> (75.25, -75.25)
  line L13 (-75.25, -75.25) -> (75.25, 75.25)
  line L14 (75.25, -75.25) -> (-75.25, 75.25)
  line L15 (-81.2, 81.2) -> (81.2, 81.2)
  line L16 (-81.2, -81.2) -> (-81.2, 81.2)
  line L17 (81.2, -81.2) -> (-81.2, -81.2)
  line L18 (81.2, 81.2) -> (81.2, -81.2)
  line L19 (-81.2, -81.2) -> (81.2, 81.2)
  line L20 (81.2, -81.2) -> (-81.2, 81.2)
  point P14 (0, 0)
  point P1 (0, 0)
  point P19 (0, 0)
  point P7 (81.2, 81.2)
  point P15 (81.2, 81.2)
  point P11 (-75.25, 75.25)
  point P12 (-75.25, -75.25)
  point P13 (75.25, -75.25)
  horizontal L9
  perpendicular L9 L10
  parallel L9 L11
  parallel L10 L12
  coincident L13 P14
  coincident L14 P14
  coincident P1 P14
  horizontal L15
  perpendicular L15 L16
  parallel L15 L17
  parallel L16 L18
  coincident L19 P19
  coincident L20 P19
  coincident P7 P15
  coincident P1 P19
  dimension "d50" distance P11 P12 = 150.5
  dimension "d51" distance P12 P13 = 150.5
extrude "Extrude7" add sketch "Sketch14" profile of L1 L2 L3 L4 L5 L6 L7 L8 L9 L10 L11 L12 L15 L16 L17 L18 along normal blind 30
fillet "Fillet1" radius 3
named bodies: "intake", "strainer Frame"

design "Fam2defuser"
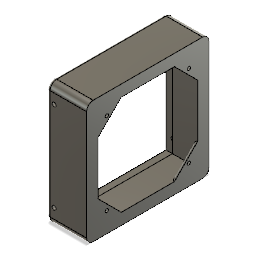
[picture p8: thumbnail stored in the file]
named bodies: "defuser holder"

design "fan housing"
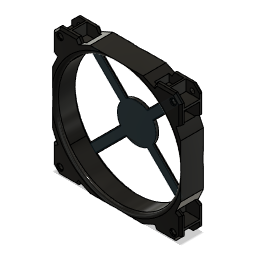
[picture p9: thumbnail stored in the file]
sketch "Sketch1" plane through (0, 0, 0) normal (0, 0, 1) x axis (1, 0, 0)
  line L1 (-70, 70) -> (70, 70)
  line L2 (-70, -70) -> (-70, 70)
  line L3 (70, -70) -> (-70, -70)
  line L4 (70, 70) -> (70, -70)
  line L5 (-70, -70) -> (70, 70)
  line L6 (70, -70) -> (-70, 70)
  circle C1 centre (0, 0) radius 67.5
  point P6 (0, 0)
  point P1 (0, 0)
  point P7 (0, 0)
  point P4 (-70, -70)
  point P5 (70, -70)
  point P3 (-70, 70)
  horizontal L1
  perpendicular L1 L2
  parallel L1 L3
  parallel L2 L4
  coincident L5 P6
  coincident L6 P6
  coincident P1 P6
  coincident P1 P7
  dimension "d1" distance P4 P5 = 140
  dimension "d2" distance P3 P4 = 140
  dimension "d3" diameter C1 = 135
extrude "Extrude1" new body sketch "Sketch1" profile of L1 L2 L3 L4 C1 along normal blind 25
sketch "Sketch2" plane through (0, 0, 25) normal (0, 0, 1) x axis (1, 0, 0)
  line L1 (70, 70) -> (70, -70)
  line L2 (-70, 70) -> (70, 70)
  line L3 (-70, -70) -> (-70, 70)
  line L4 (70, -70) -> (-70, -70)
  line L5 (-62.9289, 70) -> (-70, 62.9289)
  line L6 (-70, 70) -> (-70, 62.9289)
  line L7 (0, 70) -> (0, 0)
  line L8 (70, 0) -> (0, 0)
  line L9 (62.9289, 70) -> (70, 62.9289)
  line L10 (70, 70) -> (-70, 70)
  line L11 (70, 70) -> (70, 62.9289)
  line L12 (-62.9289, -70) -> (-70, -62.9289)
  line L13 (62.9289, -70) -> (70, -62.9289)
  line L14 (-70, -70) -> (-70, -62.9289)
  line L15 (70, -70) -> (62.9289, -70)
  line L16 (70, -70) -> (70, -62.9289)
  line L17 (-70, -70) -> (-62.9289, -70)
  circle C1 centre (0, 0) radius 67.5
  point P7 (-70, 62.9289)
  point P8 (-62.9289, 70)
  point P5 (-70, 70)
  point P9 (-70, 70)
  point P1 (0, 0)
  point P10 (0, 0)
  point P11 (0, 70)
  point P12 (0, 0)
  point P13 (70, 0)
  point P4 (70, 70)
  point P16 (-70, 70)
  point P17 (70, 70)
  point P14 (70, 62.9289)
  point P15 (62.9289, 70)
  point P18 (70, 70)
  point P19 (-70, -62.9289)
  point P20 (-62.9289, -70)
  point P21 (70, -62.9289)
  point P22 (62.9289, -70)
  point P6 (-70, -70)
  point P23 (-70, -70)
  point P3 (70, -70)
  point P24 (70, -70)
  coincident L3 P7
  coincident L2 P8
  coincident P5 P9
  coincident P1 P10
  midpoint L2 P11
  coincident P1 P12
  midpoint L1 P13
  symmetric P4 L7 P16
  symmetric P5 L7 P17
  symmetric P7 L7 P14
  symmetric P8 L7 P15
  symmetric P9 L7 P18
  symmetric P7 L8 P19
  symmetric P8 L8 P20
  symmetric L8 P14 P21
  symmetric L8 P15 P22
  coincident P6 P23
  coincident P3 P24
  dimension "d6" angle L2 L5 = 45
  dimension "d7" distance P7 P8 = 10
extrude "Extrude2" cut sketch "Sketch2" profile of L1 L2 L3 L4 L5 L6 L9 L10 L11 L12 L13 L14 L15 L16 L17 against normal blind 25
sketch "Sketch3" plane through (0, 0, 25) normal (0, 0, 1) x axis (1, 0, 0)
  line L1 (-62.9289, -70) -> (-70, -62.9289)
  line L2 (62.9289, -70) -> (-62.9289, -70)
  line L3 (70, -62.9289) -> (62.9289, -70)
  line L4 (70, 62.9289) -> (70, -62.9289)
  line L5 (62.9289, 70) -> (70, 62.9289)
  line L6 (-62.9289, 70) -> (62.9289, 70)
  line L7 (-70, 62.9289) -> (-62.9289, 70)
  line L8 (-70, -62.9289) -> (-70, 62.9289)
  line L9 (-40.0422, 65) -> (-42.9289, 70)
  line L10 (-28.9289, 70) -> (-40.0422, 65)
  line L11 (-28.9289, 70) -> (-42.9289, 70)
  line L12 (0, 70) -> (0, 0)
  line L13 (0, 0) -> (70, 0)
  line L14 (28.9289, 70) -> (40.0422, 65)
  line L15 (40.0422, 65) -> (42.9289, 70)
  line L16 (28.9289, 70) -> (42.9289, 70)
  line L17 (-28.9289, -70) -> (-40.0422, -65)
  line L18 (-40.0422, -65) -> (-42.9289, -70)
  line L19 (28.9289, -70) -> (40.0422, -65)
  line L20 (40.0422, -65) -> (42.9289, -70)
  line L21 (-28.9289, -70) -> (-42.9289, -70)
  line L22 (42.9289, -70) -> (28.9289, -70)
  line L23 (66.4645, 66.4645) -> (0, 0)
  line L24 (66.4645, 66.4645) -> (0, 0)
  line L25 (70, 28.9289) -> (65, 40.0422)
  line L26 (65, 40.0422) -> (70, 42.9289)
  line L27 (70, 28.9289) -> (70, 42.9289)
  line L28 (-65, 40.0422) -> (-70, 42.9289)
  line L29 (-70, 28.9289) -> (-65, 40.0422)
  line L30 (-70, 28.9289) -> (-70, 42.9289)
  line L31 (-65, -40.0422) -> (-70, -42.9289)
  line L32 (-70, -28.9289) -> (-65, -40.0422)
  line L33 (65, -40.0422) -> (70, -42.9289)
  line L34 (70, -28.9289) -> (65, -40.0422)
  circle C1 centre (0, 0) radius 67.5
  point P11 (-42.9289, 70)
  point P13 (-28.9289, 70)
  point P10 (0, 0)
  point P14 (0, 0)
  point P15 (0, 70)
  point P16 (70, 0)
  point P17 (0, 0)
  point P20 (42.9289, 70)
  point P12 (-40.0422, 65)
  point P18 (40.0422, 65)
  point P19 (28.9289, 70)
  point P23 (-42.9289, -70)
  point P21 (-40.0422, -65)
  point P22 (-28.9289, -70)
  point P24 (40.0422, -65)
  point P25 (28.9289, -70)
  point P26 (42.9289, -70)
  point P27 (66.4645, 66.4645)
  point P28 (0, 0)
  point P30 (65, 40.0422)
  point P31 (70, 28.9289)
  point P32 (70, 42.9289)
  point P29 (66.4645, 66.4645)
  point P34 (-65, 40.0422)
  point P35 (-70, 28.9289)
  point P33 (-70, 42.9289)
  point P40 (65, -40.0422)
  point P41 (70, -28.9289)
  point P39 (70, -42.9289)
  point P36 (-70, -42.9289)
  point P37 (-65, -40.0422)
  point P38 (-70, -28.9289)
  point P8 (-62.9289, 70)
  coincident L6 P11
  coincident L6 P13
  coincident P10 P14
  midpoint L6 P15
  midpoint L4 P16
  coincident P10 P17
  symmetric P11 L12 P20
  symmetric P12 L12 P18
  symmetric P13 L12 P19
  symmetric P11 L13 P23
  symmetric P12 L13 P21
  symmetric P13 L13 P22
  symmetric L13 P18 P24
  symmetric L13 P19 P25
  symmetric L13 P20 P26
  midpoint L5 P27
  symmetric P14 L23 P28
  symmetric P18 L23 P30
  symmetric P19 L23 P31
  symmetric P20 L23 P32
  symmetric P27 L23 P29
  symmetric L12 P30 P34
  symmetric L12 P31 P35
  symmetric L12 P32 P33
  symmetric L13 P30 P40
  symmetric L13 P31 P41
  symmetric L13 P32 P39
  symmetric L13 P33 P36
  symmetric L13 P34 P37
  symmetric L13 P35 P38
  dimension "d10" distance P8 P11 = 20
  dimension "d11" distance P8 P13 = 34
  dimension "d12" distance L6 P12 = 5
  dimension "d13" angle L7 L9 = 75
extrude "Extrude3" cut sketch "Sketch3" profile of L2 L4 L6 L8 L9 L10 L11 L14 L15 L16 L17 L18 L19 L20 L21 L22 L25 L26 L27 L28 L29 L30 L31 L32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 against normal blind 25
sketch "Sketch4" plane through (0, 0, 25) normal (0, 0, 1) x axis (1, 0, 0)
  line L1 (70, -28.9289) -> (65, -40.0422)
  line L2 (70, 28.9289) -> (70, -28.9289)
  line L3 (65, 40.0422) -> (70, 28.9289)
  line L4 (70, 42.9289) -> (65, 40.0422)
  line L5 (70, 62.9289) -> (70, 42.9289)
  line L6 (62.9289, 70) -> (70, 62.9289)
  line L7 (42.9289, 70) -> (62.9289, 70)
  line L8 (40.0422, 65) -> (42.9289, 70)
  line L9 (28.9289, 70) -> (40.0422, 65)
  line L10 (-28.9289, 70) -> (28.9289, 70)
  line L11 (-40.0422, 65) -> (-28.9289, 70)
  line L12 (-42.9289, 70) -> (-40.0422, 65)
  line L13 (-62.9289, 70) -> (-42.9289, 70)
  line L14 (-70, 62.9289) -> (-62.9289, 70)
  line L15 (-70, 42.9289) -> (-70, 62.9289)
  line L16 (-65, 40.0422) -> (-70, 42.9289)
  line L17 (-70, 28.9289) -> (-65, 40.0422)
  line L18 (-70, -28.9289) -> (-70, 28.9289)
  line L19 (-65, -40.0422) -> (-70, -28.9289)
  line L20 (-70, -42.9289) -> (-65, -40.0422)
  line L21 (-70, -62.9289) -> (-70, -42.9289)
  line L22 (-62.9289, -70) -> (-70, -62.9289)
  line L23 (-42.9289, -70) -> (-62.9289, -70)
  line L24 (-40.0422, -65) -> (-42.9289, -70)
  line L25 (-28.9289, -70) -> (-40.0422, -65)
  line L26 (28.9289, -70) -> (-28.9289, -70)
  line L27 (40.0422, -65) -> (28.9289, -70)
  line L28 (42.9289, -70) -> (40.0422, -65)
  line L29 (62.9289, -70) -> (42.9289, -70)
  line L30 (70, -62.9289) -> (62.9289, -70)
  line L31 (70, -42.9289) -> (70, -62.9289)
  line L32 (65, -40.0422) -> (70, -42.9289)
  line L33 (-66.4645, 66.4645) -> (0, 0)
  line L34 (-67.5, 0) -> (0, 0)
  line L35 (0, 67.5) -> (0, 0)
  line L36 (-66.4645, 66.4645) -> (-64.3431, 64.3431)
  circle C1 centre (0, 0) radius 67.5
  circle C2 centre (-61.8683, 61.8683) radius 3.5
  circle C3 centre (61.8683, 61.8683) radius 3.5
  circle C4 centre (61.8683, -61.8683) radius 3.5
  circle C5 centre (-61.8683, -61.8683) radius 3.5
  point P1 (0, 0)
  point P35 (0, 0)
  point P36 (-66.4645, 66.4645)
  point P34 (0, 0)
  point P37 (0, 0)
  point P38 (-67.5, 0)
  point P39 (0, 0)
  point P40 (0, 67.5)
  point P41 (-61.8683, 61.8683)
  point P42 (-64.3431, 64.3431)
  coincident P1 P35
  midpoint L14 P36
  coincident P34 P37
  coincident C1 P38
  perpendicular L2 L34
  coincident P34 P39
  perpendicular L34 L35
  coincident C1 P40
  coincident L33 P41
  coincident C2 P42
  coincident L33 P42
  perpendicular L14 L36
  symmetric L35 C2 C3
  symmetric L34 C2 C5
  symmetric L34 C3 C4
  dimension "d16" diameter C2 = 7
  dimension "d17" distance P36 P42 = 3
extrude "Extrude4" cut sketch "Sketch4" profile of C2 C3 C4 C5 against normal blind 1.2
sketch "Sketch5" plane through (0, 0, 25) normal (0, 0, 1) x axis (1, 0, 0)
  line L1 (70, -28.9289) -> (65, -40.0422)
  line L2 (70, 28.9289) -> (70, -28.9289)
  line L3 (65, 40.0422) -> (70, 28.9289)
  line L4 (70, 42.9289) -> (65, 40.0422)
  line L5 (70, 62.9289) -> (70, 42.9289)
  line L6 (62.9289, 70) -> (70, 62.9289)
  line L7 (42.9289, 70) -> (62.9289, 70)
  line L8 (40.0422, 65) -> (42.9289, 70)
  line L9 (28.9289, 70) -> (40.0422, 65)
  line L10 (-28.9289, 70) -> (28.9289, 70)
  line L11 (-40.0422, 65) -> (-28.9289, 70)
  line L12 (-42.9289, 70) -> (-40.0422, 65)
  line L13 (-62.9289, 70) -> (-42.9289, 70)
  line L14 (-70, 62.9289) -> (-62.9289, 70)
  line L15 (-70, 42.9289) -> (-70, 62.9289)
  line L16 (-65, 40.0422) -> (-70, 42.9289)
  line L17 (-70, 28.9289) -> (-65, 40.0422)
  line L18 (-70, -28.9289) -> (-70, 28.9289)
  line L19 (-65, -40.0422) -> (-70, -28.9289)
  line L20 (-70, -42.9289) -> (-65, -40.0422)
  line L21 (-70, -62.9289) -> (-70, -42.9289)
  line L22 (-62.9289, -70) -> (-70, -62.9289)
  line L23 (-42.9289, -70) -> (-62.9289, -70)
  line L24 (-40.0422, -65) -> (-42.9289, -70)
  line L25 (-28.9289, -70) -> (-40.0422, -65)
  line L26 (28.9289, -70) -> (-28.9289, -70)
  line L27 (40.0422, -65) -> (28.9289, -70)
  line L28 (42.9289, -70) -> (40.0422, -65)
  line L29 (62.9289, -70) -> (42.9289, -70)
  line L30 (70, -62.9289) -> (62.9289, -70)
  line L31 (70, -42.9289) -> (70, -62.9289)
  line L32 (65, -40.0422) -> (70, -42.9289)
  circle C1 centre (-61.8683, -61.8683) radius 3.5
  circle C2 centre (61.8683, -61.8683) radius 3.5
  circle C3 centre (-61.8683, 61.8683) radius 3.5
  circle C4 centre (61.8683, 61.8683) radius 3.5
  circle C5 centre (0, 0) radius 67.5
  circle C6 centre (-61.8683, 61.8683) radius 2.5
  circle C7 centre (-61.8683, -61.8683) radius 2.5
  circle C8 centre (61.8683, -61.8683) radius 2.5
  circle C9 centre (61.8683, 61.8683) radius 2.5
  concentric C3 C6
  concentric C1 C7
  concentric C2 C8
  concentric C4 C9
  dimension "d20" diameter C6 = 5
  dimension "d21" diameter C7 = 5
  dimension "d22" diameter C8 = 5
  dimension "d23" diameter C9 = 5
extrude "Extrude5" cut sketch "Sketch5" profile of C6 C7 C8 C9 against normal blind 25
sketch "Sketch6" plane through (70, 0, 0) normal (1, 0, 0) x axis (0, 0, -1)
  line L1 (0, 42.9289) -> (-25, 42.9289)
  line L2 (0, 62.9289) -> (0, 42.9289)
  line L3 (-25, 62.9289) -> (0, 62.9289)
  line L4 (-25, 42.9289) -> (-25, 62.9289)
  line L5 (-4, 73) -> (-21, 73)
  line L6 (-4, 58) -> (-4, 73)
  line L7 (-21, 58) -> (-4, 58)
  line L8 (-21, 73) -> (-21, 58)
  line L9 (0, 70) -> (-25, 70)
  line L10 (-39.3823, 0) -> (0, 0)
  line L11 (-4, -73) -> (-21, -73)
  line L12 (-21, -73) -> (-21, -58)
  line L13 (-4, -58) -> (-4, -73)
  line L14 (-21, -58) -> (-4, -58)
  line L15 (-12.5, 74.549) -> (-12.5, 0)
  line L16 (-25, 70) -> (-25, 62.9289)
  point P1 (0, 0)
  point P12 (0, 0)
  point P6 (-21, 73)
  point P14 (-21, -73)
  point P7 (-4, 73)
  point P15 (-4, -73)
  point P8 (-4, 58)
  point P17 (-4, -58)
  point P9 (-21, 58)
  point P16 (-21, -58)
  point P18 (-12.5, 0)
  horizontal L5
  vertical L6
  horizontal L7
  vertical L8
  coincident P1 P12
  horizontal L10
  symmetric P6 L10 P14
  symmetric P7 L10 P15
  symmetric P8 L10 P17
  symmetric P9 L10 P16
  coincident L10 P18
  parallel L2 L15
  symmetric L6 L8 L15
  dimension "d26" distance L7 L9 = 12
  dimension "d27" distance P6 P9 = 15
  dimension "d28" distance P6 P7 = 17
  dimension "d29" distance L15 L16 = 12.5 (= "( 25 / 2 ) * 1 mm")
extrude "Extrude6" cut sketch "Sketch6" profile of L3 L5 L6 L7 L8 L9 L11 L12 L13 L14 L15 against normal blind 15
sketch "Sketch7" plane through (-70, 0, 0) normal (-1, 0, 0) x axis (0, 0, 1)
  line L1 (25, 42.9289) -> (0, 42.9289)
  line L2 (25, 62.9289) -> (25, 42.9289)
  line L3 (0, 62.9289) -> (25, 62.9289)
  line L4 (0, 42.9289) -> (0, 62.9289)
  line L5 (21, 73) -> (4, 73)
  line L6 (21, 58) -> (21, 73)
  line L7 (4, 58) -> (21, 58)
  line L8 (4, 73) -> (4, 58)
  line L9 (25, 70) -> (0, 70)
  line L10 (25, 0) -> (0, 0)
  line L11 (12.5, 0) -> (12.5, 70)
  line L12 (21, -73) -> (4, -73)
  line L13 (21, -58) -> (21, -73)
  line L14 (4, -73) -> (4, -58)
  line L15 (4, -58) -> (21, -58)
  point P1 (0, 0)
  point P12 (0, 0)
  point P14 (12.5, 70)
  point P15 (12.5, 0)
  point P6 (4, 73)
  point P16 (4, -73)
  point P7 (21, 73)
  point P17 (21, -73)
  point P8 (21, 58)
  point P18 (21, -58)
  point P9 (4, 58)
  point P19 (4, -58)
  horizontal L5
  vertical L6
  horizontal L7
  vertical L8
  coincident P1 P12
  horizontal L10
  midpoint L9 P14
  midpoint L10 P15
  symmetric L6 L8 L11
  symmetric P6 L10 P16
  symmetric P7 L10 P17
  symmetric P8 L10 P18
  symmetric P9 L10 P19
  dimension "d32" distance P8 L9 = 12
  dimension "d33" distance L5 L7 = 15
  dimension "d34" distance L6 L8 = 17
extrude "Extrude7" cut sketch "Sketch7" profile of L3 L5 L6 L7 L8 L9 L12 L13 L14 L15 against normal blind 15
sketch "Sketch8" plane through (-70, 0, 0) normal (-1, 0, 0) x axis (0, 0, 1)
  line L1 (21, 58) -> (21, 62.9289)
  line L2 (4, 58) -> (21, 58)
  line L3 (4, 62.9289) -> (4, 58)
  line L4 (0, 62.9289) -> (4, 62.9289)
  line L5 (0, 42.9289) -> (0, 62.9289)
  line L6 (25, 42.9289) -> (0, 42.9289)
  line L7 (25, 62.9289) -> (25, 42.9289)
  line L8 (21, 62.9289) -> (25, 62.9289)
  line L9 (21.105, 55.5) -> (4.105, 55.5)
  line L10 (21.105, 39.5) -> (21.105, 55.5)
  line L11 (4.105, 39.5) -> (21.105, 39.5)
  line L12 (4.105, 55.5) -> (4.105, 39.5)
  line L13 (34.0895, 0) -> (0, 0)
  line L14 (4.105, -55.5) -> (4.105, -39.5)
  line L15 (21.105, -55.5) -> (4.105, -55.5)
  line L16 (21.105, -39.5) -> (21.105, -55.5)
  line L17 (4.105, -39.5) -> (21.105, -39.5)
  point P1 (0, 0)
  point P14 (0, 0)
  point P10 (4.105, 55.5)
  point P17 (4.105, -55.5)
  point P11 (21.105, 55.5)
  point P18 (21.105, -55.5)
  point P12 (21.105, 39.5)
  point P19 (21.105, -39.5)
  point P13 (4.105, 39.5)
  point P16 (4.105, -39.5)
  horizontal L9
  vertical L10
  horizontal L11
  vertical L12
  coincident P1 P14
  perpendicular L5 L13
  symmetric P10 L13 P17
  symmetric P11 L13 P18
  symmetric P12 L13 P19
  symmetric P13 L13 P16
  dimension "d37" distance P10 P13 = 16
  dimension "d38" distance L11 L13 = 39.5
  dimension "d39" distance P10 P11 = 17
extrude "Extrude8" cut sketch "Sketch8" profile of L6 L9 L10 L11 L12 L14 L15 L16 L17 against normal blind 15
